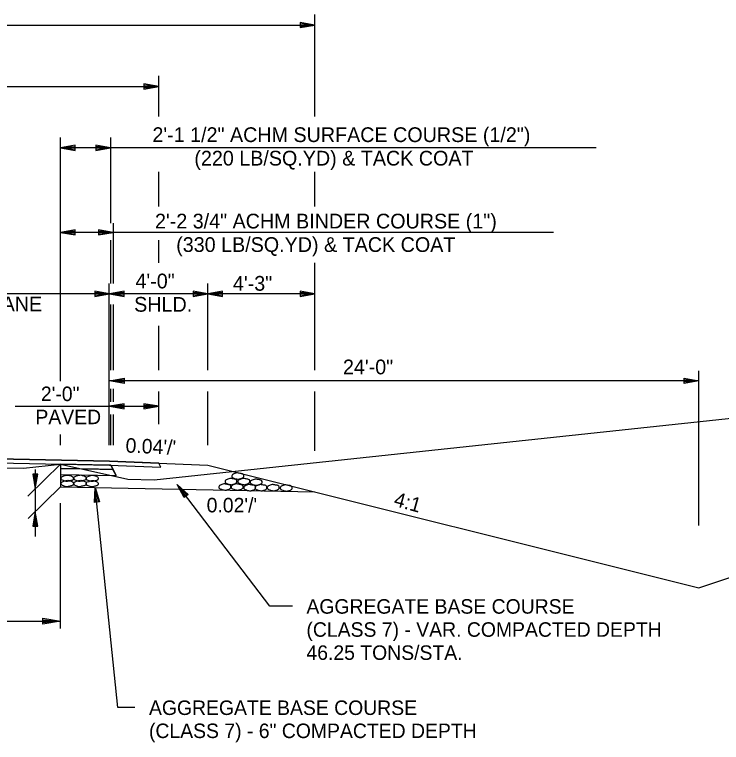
# Model space of a CAD drawing. Extents: x 1461846 to 1462006, y 1686171 to 1686805.
# Drawn here: x 1461933.18 to 1461961.96, y 1686235.2 to 1686264.82 of the extents above; entities that cross this region are included whole.
import ezdxf

# ---------------------------------------------------------------- set-up
doc = ezdxf.new("R2010")
doc.units = 0
for name, color, linetype in [('1', 7, 'Continuous'), ('19', 7, 'Continuous'), ('20', 7, 'Continuous'), ('42', 7, 'Continuous'), ('Level 1', 7, 'Continuous'), ('Level 9', 7, 'Continuous'), ('R_Draft', 7, 'Continuous')]:
    doc.layers.add(name, color=color, linetype=linetype)

# ---------------------------------------------------------------- blocks, each defined once
blk = doc.blocks.new('ROCKS')
at = {"layer": '1'}
blk.add_spline([(0.013, 0.06), (0.053, 0.053), (0.107, 0.033), (0.133, 0.013), (0.133, -0.007), (0.12, -0.033), (0.107, -0.04), (0.073, -0.053), (0.033, -0.067), (0.013, -0.067), (-0.02, -0.06), (-0.06, -0.053), (-0.087, -0.047), (-0.113, -0.02), (-0.113, -0.007), (-0.107, 0.02), (-0.087, 0.033), (-0.067, 0.047), (-0.033, 0.053), (-0.02, 0.06), (0.013, 0.06)], degree=3, dxfattribs=at)
blk = doc.blocks.new('4TO1 ABC')
at = {"layer": '1', "xscale": 0.1312491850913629, "yscale": 0.1312491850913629, "rotation": 180}
for p in [(0.00175, -0.00875), (-0.016625, -0.023625), (0.018375, -0.023625), (0.051625, -0.025375), (-0.03325, -0.0385), (0, -0.0385), (0.034125, -0.04025), (0.06475, -0.04025), (0.098, -0.04025), (0.133, -0.041125)]:
    blk.add_blockref('ROCKS', p, dxfattribs=at)

msp = doc.modelspace()

# ---------------------------------------------------------------- linework, layer by layer
at = {"layer": '19'}
for p, q in [((1461944.806, 1686264.503), (1461944.806, 1686264.293)), ((1461945.406, 1686264.398), (1461944.806, 1686264.503)), ((1461945.246, 1686264.413), (1461944.806, 1686264.448)), ((1461906.686, 1686264.398), (1461945.406, 1686264.398)), ((1461944.806, 1686264.293), (1461945.406, 1686264.398)), ((1461944.806, 1686264.343), (1461945.246, 1686264.383)), ((1461913.046, 1686261.898), (1461939.046, 1686261.898)), ((1461938.446, 1686262.003), (1461938.446, 1686261.793)), ((1461939.046, 1686261.898), (1461938.446, 1686262.003)), ((1461938.886, 1686261.913), (1461938.446, 1686261.948)), ((1461938.446, 1686261.793), (1461939.046, 1686261.898)), ((1461938.446, 1686261.843), (1461938.886, 1686261.883)), ((1461935.646, 1686259.502), (1461935.046, 1686259.397)), ((1461956.864, 1686259.397), (1461935.046, 1686259.397)), ((1461935.046, 1686259.397), (1461935.646, 1686259.292)), ((1461935.646, 1686259.447), (1461935.206, 1686259.412)), ((1461935.646, 1686259.292), (1461935.646, 1686259.502)), ((1461936.488, 1686259.503), (1461936.488, 1686259.293)), ((1461937.088, 1686259.397), (1461936.488, 1686259.503)), ((1461936.928, 1686259.412), (1461936.488, 1686259.448)), ((1461936.488, 1686259.293), (1461937.088, 1686259.397)), ((1461935.206, 1686259.382), (1461935.646, 1686259.342)), ((1461936.488, 1686259.343), (1461936.928, 1686259.382)), ((1461935.646, 1686256.063), (1461935.046, 1686255.958)), ((1461935.046, 1686255.958), (1461935.646, 1686255.853)), ((1461955.12, 1686255.957), (1461935.051, 1686255.957)), ((1461935.646, 1686256.008), (1461935.206, 1686255.973)), ((1461935.206, 1686255.943), (1461935.646, 1686255.903)), ((1461935.646, 1686255.853), (1461935.646, 1686256.063)), ((1461936.593, 1686256.062), (1461936.593, 1686255.852)), ((1461937.193, 1686255.957), (1461936.593, 1686256.062)), ((1461937.033, 1686255.972), (1461936.593, 1686256.007)), ((1461936.593, 1686255.852), (1461937.193, 1686255.957)), ((1461936.593, 1686255.902), (1461937.033, 1686255.942)), ((1461936.446, 1686253.562), (1461936.446, 1686253.352)), ((1461937.046, 1686253.457), (1461936.446, 1686253.562)), ((1461936.886, 1686253.472), (1461936.446, 1686253.507)), ((1461937.646, 1686253.562), (1461937.046, 1686253.457)), ((1461937.646, 1686253.507), (1461937.206, 1686253.472)), ((1461937.646, 1686253.352), (1461937.646, 1686253.562)), ((1461940.446, 1686253.562), (1461940.446, 1686253.352)), ((1461941.046, 1686253.457), (1461940.446, 1686253.562)), ((1461940.886, 1686253.472), (1461940.446, 1686253.507)), ((1461941.646, 1686253.562), (1461941.046, 1686253.457)), ((1461941.646, 1686253.507), (1461941.206, 1686253.472)), ((1461941.646, 1686253.352), (1461941.646, 1686253.562)), ((1461944.806, 1686253.562), (1461944.806, 1686253.352)), ((1461945.406, 1686253.457), (1461944.806, 1686253.562)), ((1461945.246, 1686253.472), (1461944.806, 1686253.507)), ((1461936.446, 1686253.352), (1461937.046, 1686253.457)), ((1461936.446, 1686253.402), (1461936.886, 1686253.442)), ((1461937.046, 1686253.457), (1461937.646, 1686253.352)), ((1461937.206, 1686253.442), (1461937.646, 1686253.402)), ((1461940.446, 1686253.352), (1461941.046, 1686253.457)), ((1461940.446, 1686253.402), (1461940.886, 1686253.442)), ((1461941.046, 1686253.457), (1461941.646, 1686253.352)), ((1461941.206, 1686253.442), (1461941.646, 1686253.402)), ((1461944.806, 1686253.352), (1461945.406, 1686253.457)), ((1461944.806, 1686253.402), (1461945.246, 1686253.442)), ((1461937.046, 1686249.917), (1461937.646, 1686250.022)), ((1461937.646, 1686249.812), (1461937.046, 1686249.917)), ((1461937.206, 1686249.932), (1461937.646, 1686249.967)), ((1461937.646, 1686250.022), (1461937.646, 1686249.812)), ((1461960.446, 1686249.812), (1461960.446, 1686250.022)), ((1461960.446, 1686250.022), (1461961.046, 1686249.917)), ((1461960.446, 1686249.967), (1461960.886, 1686249.932)), ((1461961.046, 1686249.917), (1461960.446, 1686249.812)), ((1461937.646, 1686249.862), (1461937.206, 1686249.902)), ((1461960.886, 1686249.902), (1461960.446, 1686249.862)), ((1461933.203, 1686248.881), (1461939.046, 1686248.881)), ((1461937.646, 1686248.986), (1461937.046, 1686248.881)), ((1461937.046, 1686248.881), (1461937.646, 1686248.776)), ((1461937.646, 1686248.931), (1461937.206, 1686248.896)), ((1461937.206, 1686248.866), (1461937.646, 1686248.826)), ((1461937.646, 1686248.776), (1461937.646, 1686248.986)), ((1461938.446, 1686248.986), (1461938.446, 1686248.776)), ((1461939.046, 1686248.881), (1461938.446, 1686248.986)), ((1461938.886, 1686248.896), (1461938.446, 1686248.931)), ((1461938.446, 1686248.776), (1461939.046, 1686248.881)), ((1461938.446, 1686248.826), (1461938.886, 1686248.866)), ((1461937.046, 1686246.648), (1461926.046, 1686246.868)), ((1461926.046, 1686246.701), (1461937.046, 1686246.481)), ((1461939.046, 1686246.568), (1461937.046, 1686246.648)), ((1461935.046, 1686246.521), (1461935.046, 1686245.605)), ((1461936.977, 1686246.483), (1461935.046, 1686246.521)), ((1461935.046, 1686246.521), (1461935.046, 1686246.521)), ((1461935.046, 1686246.521), (1461935.046, 1686246.521)), ((1461935.046, 1686246.521), (1461935.046, 1686246.521)), ((1461935.046, 1686246.354), (1461936.787, 1686246.32)), ((1461935.046, 1686246.354), (1461935.046, 1686246.354)), ((1461935.046, 1686246.354), (1461935.046, 1686246.104)), ((1461937.102, 1686246.478), (1461936.977, 1686246.483)), ((1461937.046, 1686246.481), (1461939.131, 1686246.398)), ((1461937.046, 1686246.481), (1461939.131, 1686246.398)), ((1461937.102, 1686246.478), (1461937.312, 1686246.059)), ((1461937.18, 1686246.322), (1461937.102, 1686246.478)), ((1461939.131, 1686246.398), (1461939.046, 1686246.568)), ((1461934.128, 1686246.12), (1461933.918, 1686246.12)), ((1461933.918, 1686246.12), (1461934.023, 1686245.52)), ((1461933.973, 1686246.12), (1461934.008, 1686245.68)), ((1461934.023, 1686245.52), (1461934.128, 1686246.12)), ((1461934.038, 1686245.68), (1461934.078, 1686246.12)), ((1461935.046, 1686246.104), (1461937.312, 1686246.059)), ((1461935.046, 1686246.104), (1461935.046, 1686246.104)), ((1461936.787, 1686246.32), (1461937.18, 1686246.322)), ((1461937.312, 1686246.059), (1461937.185, 1686246.312)), ((1461936.428, 1686244.97), (1461936.466, 1686245.576)), ((1461937.378, 1686236.618), (1461936.466, 1686245.576)), ((1461936.466, 1686245.576), (1461936.636, 1686244.991)), ((1461943.57, 1686240.742), (1461939.794, 1686245.7)), ((1461940.081, 1686245.164), (1461939.794, 1686245.7)), ((1461939.794, 1686245.7), (1461940.246, 1686245.292)), ((1461940.119, 1686245.195), (1461939.88, 1686245.565)), ((1461939.902, 1686245.582), (1461940.202, 1686245.261)), ((1461936.477, 1686244.976), (1461936.467, 1686245.416)), ((1461936.496, 1686245.419), (1461936.583, 1686244.988)), ((1461940.246, 1686245.292), (1461940.081, 1686245.164)), ((1461936.636, 1686244.991), (1461936.428, 1686244.97)), ((1461934.023, 1686244.598), (1461933.918, 1686243.998)), ((1461934.128, 1686243.998), (1461934.023, 1686244.598)), ((1461934.008, 1686244.438), (1461933.968, 1686243.998)), ((1461934.073, 1686243.998), (1461934.038, 1686244.438)), ((1461933.918, 1686243.998), (1461934.128, 1686243.998)), ((1461944.493, 1686240.742), (1461943.57, 1686240.742)), ((1461938.081, 1686236.618), (1461937.378, 1686236.618))]:
    msp.add_line(p, q, dxfattribs=at)
for points in [[(1461935.046, 1686246.521), (1461935.046, 1686246.521), (1461935.046, 1686246.521), (1461935.046, 1686246.521)], [(1461935.046, 1686246.521), (1461935.046, 1686246.521), (1461935.046, 1686246.354)], [(1461937.185, 1686246.312), (1461936.598, 1686246.323), (1461935.046, 1686246.354)]]:
    msp.add_lwpolyline(points, dxfattribs=at)
at = {"layer": '20'}
for p, q in [((1461937.088, 1686259.825), (1461937.088, 1686256.34)), ((1461937.193, 1686256.34), (1461937.193, 1686253.884)), ((1461937.088, 1686255.636), (1461937.088, 1686253.884)), ((1461937.088, 1686253.028), (1461937.088, 1686250.346)), ((1461937.193, 1686253.028), (1461937.193, 1686250.346)), ((1461937.088, 1686249.59), (1461937.088, 1686249.06)), ((1461937.193, 1686249.59), (1461937.193, 1686249.06)), ((1461937.088, 1686248.54), (1461937.088, 1686247.293)), ((1461937.193, 1686248.54), (1461937.193, 1686247.293)), ((1461935.047, 1686246.522), (1461933.724, 1686245.228)), ((1461935.051, 1686245.604), (1461933.728, 1686244.31)), ((1461935.046, 1686239.832), (1461935.046, 1686244.931)), ((1461915.046, 1686240.132), (1461935.046, 1686240.132)), ((1461934.33, 1686240.006), (1461934.33, 1686240.257)), ((1461934.33, 1686240.257), (1461935.046, 1686240.132)), ((1461934.33, 1686240.191), (1461934.855, 1686240.149)), ((1461935.046, 1686240.132), (1461934.33, 1686240.006)), ((1461934.855, 1686240.114), (1461934.33, 1686240.066))]:
    msp.add_line(p, q, dxfattribs=at)
for points in [[(1461937.017, 1686253.884), (1461937.017, 1686253.884), (1461937.017, 1686253.884), (1461937.017, 1686247.293)], [(1461934.023, 1686246.312), (1461934.023, 1686243.582)]]:
    msp.add_lwpolyline(points, dxfattribs=at)
at = {"layer": 'Level 9'}
for p, q in [((1461945.406, 1686260.675), (1461945.406, 1686264.824)), ((1461939.046, 1686260.675), (1461939.046, 1686262.324)), ((1461935.046, 1686256.384), (1461935.046, 1686259.825)), ((1461935.046, 1686249.904), (1461935.046, 1686259.825)), ((1461939.046, 1686257.007), (1461939.046, 1686258.429)), ((1461945.406, 1686257.007), (1461945.406, 1686258.429)), ((1461939.046, 1686254.714), (1461939.046, 1686255.636)), ((1461945.406, 1686250.346), (1461945.406, 1686254.714)), ((1461941.046, 1686250.346), (1461941.046, 1686253.884)), ((1461937.046, 1686253.457), (1461926.046, 1686253.457)), ((1461945.406, 1686253.457), (1461937.046, 1686253.457)), ((1461939.046, 1686250.346), (1461939.046, 1686252.159)), ((1461961.046, 1686244.031), (1461961.046, 1686250.32)), ((1461961.046, 1686249.917), (1461937.046, 1686249.917)), ((1461939.046, 1686248.152), (1461939.046, 1686249.485)), ((1461941.046, 1686247.293), (1461941.046, 1686249.485)), ((1461945.406, 1686247.061), (1461945.406, 1686249.485)), ((1461935.046, 1686247.293), (1461935.046, 1686247.737))]:
    msp.add_line(p, q, dxfattribs=at)
at = {"layer": 'R_Draft'}
for p, q in [((1461961.046, 1686241.488), (1461978.028, 1686247.149)), ((1461926.046, 1686246.868), (1461937.046, 1686246.648)), ((1461926.046, 1686246.701), (1461937.046, 1686246.481)), ((1461937.046, 1686246.648), (1461941.046, 1686246.488)), ((1461935.046, 1686246.355), (1461937.185, 1686246.312)), ((1461941.046, 1686246.488), (1461961.046, 1686241.488)), ((1461935.046, 1686246.105), (1461937.312, 1686246.059)), ((1461935.046, 1686245.605), (1461945.408, 1686245.397))]:
    msp.add_line(p, q, dxfattribs=at)
msp.add_lwpolyline([(1461898.954, 1686241.476), (1461905.286, 1686243.936), (1461907.805, 1686244.527), (1461913.029, 1686245.425), (1461914.716, 1686245.68), (1461915.046, 1686246.481), (1461920.316, 1686246.387), (1461926.976, 1686246.462), (1461933.536, 1686246.367), (1461935.046, 1686246.521), (1461937.792, 1686245.91), (1461938.868, 1686245.881), (1461962.881, 1686248.455)], dxfattribs=at)

# ---------------------------------------------------------------- block references
at = {"layer": '19', "xscale": 14.999970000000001, "yscale": 14.999970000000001}
msp.add_blockref('4TO1 ABC', (1461942.261, 1686246.166), dxfattribs=at)
at = {"layer": 'Level 1', "xscale": 2.011654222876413, "yscale": -2.011654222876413, "rotation": -178.96569524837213}
for p in [(1461935.346, 1686245.957), (1461935.865, 1686245.958), (1461936.357, 1686245.951), (1461935.346, 1686245.741), (1461935.865, 1686245.743), (1461936.357, 1686245.736)]:
    msp.add_blockref('ROCKS', p, dxfattribs=at)

# ---------------------------------------------------------------- texts
at = {"layer": '19'}
for s, height, p in [('4\'-3"', 0.6, (1461942.071, 1686253.584)), ('2\'-0"', 0.59, (1461934.25, 1686249.092)), ('PAVED', 0.59, (1461934.027, 1686248.152)), ('AGGREGATE BASE COURSE', 0.59001, (1461945.063, 1686240.438)), ('(CLASS 7) - VAR. COMPACTED DEPTH', 0.59001, (1461945.063, 1686239.498)), ('46.25 TONS/STA.', 0.59001, (1461945.063, 1686238.558)), ('AGGREGATE BASE COURSE', 0.59001, (1461938.651, 1686236.315)), ('(CLASS 7) - 6" COMPACTED DEPTH', 0.59001, (1461938.651, 1686235.375))]:
    msp.add_text(s, height=height, dxfattribs=at).set_placement(p)
for s, rotation, p in [("0.04'/'", 357.3887, (1461937.687, 1686247)), ("0.02'/'", 360, (1461941, 1686244.562)), ('4:1', 344.5327, (1461948.584, 1686244.837))]:
    msp.add_text(s, height=0.59, rotation=rotation, dxfattribs=at).set_placement(p)
at = {"layer": '42'}
for s, height, p in [('2\'-1 1/2" ACHM SURFACE COURSE (1/2")', 0.60001, (1461938.791, 1686259.635)), ('(220 LB/SQ.YD) & TACK COAT', 0.60001, (1461940.499, 1686258.679)), ('2\'-2 3/4" ACHM BINDER COURSE (1")', 0.60001, (1461938.896, 1686256.118)), ('(330 LB/SQ.YD) & TACK COAT', 0.60001, (1461939.759, 1686255.162)), ('4\'-0"', 0.6, (1461938.101, 1686253.679)), ('TRAVEL LANE', 0.6, (1461928.861, 1686252.747)), ('SHLD.', 0.6, (1461938.047, 1686252.729))]:
    msp.add_text(s, height=height, rotation=360, dxfattribs=at).set_placement(p)
msp.add_text('24\'-0"', height=0.6, dxfattribs=at).set_placement((1461946.551, 1686250.181))

doc.saveas('drawing.dxf')
